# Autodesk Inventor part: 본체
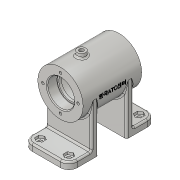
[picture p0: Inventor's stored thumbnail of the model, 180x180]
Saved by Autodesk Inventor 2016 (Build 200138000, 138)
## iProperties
Created: 2017-02
Part Number: 본체
Material: 알루미늄 6061
Document SubType Name: Modeling
Designer: H
Density: 2.7 g/cm^3
Appearance: 알루미늄 - 평지
Mass: 354.698 g
Surface Area: 422.999 cm^2
Volume: 131.37 cm^3
Author: H
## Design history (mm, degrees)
sketch "스케치2"
  geometry: C1 r 27 at (0, 0); 1 further point
  constraints: 1 centre point, 1 coincident
  dimensions: "d0" = 54 diameter of C1
extrude "돌출1" new body sketch "스케치2" stored distance "d1" = 70; taper "d2" = 0 deg
sketch "스케치4"
  geometry: L1 (-27, -35)-(27, -35) reference; L2 (27, 35)-(-27, 35) reference; L3 (0, 0)-(-60, 0); L4 (-60, 0)-(-60, 52); L5 (-60, 52)-(-52, 52); L6 (-52, 52)-(-52, 17); L7 (-52, 17)-(-60, 17) reference; L8 (-60, 17)-(-60, 52); L9 (27, -35)-(27, 35) reference; L10 (-60, -52)-(-52, -52); L11 (-52, -52)-(-52, -17); L12 (-52, -17)-(-60, -17); L13 (-60, -17)-(-60, -52)
  constraints: 20 end point, 4 symmetric about line, 3 horizontal, 2 vertical, 1 collinear, 1 perpendicular, 1 point on line
  dimensions: "d11" = 60 distance of L3.start L3.end; "d12" = 52 distance of L3.end L4.end; "d13" = 8 distance of L4.end L5.end
extrude "돌출2" join sketch "스케치4" stored distance "d17" = 54; taper "d18" = 0 deg
sketch "스케치7"
  geometry: L1 (20.591, 15)-(32, 15); L2 (32, 15)-(32, 10); L3 (32, 10)-(27, 10); L4 (-27, -35)-(27, -35) reference; L5 (27, 35)-(-27, 35) reference; L6 (27, -35)-(27, 35) reference; L7 (20.591, 15)-(20.591, 10); L8 (27, 10)-(20.591, 10); 2 further points
  constraints: 10 end point, 2 perpendicular, 1 horizontal, 1 vertical
  dimensions: "d27" = 25 vertical distance of L2.end point (27, 35); "d28" = 5 distance from line of L6 L2.end; "d108" = 25 vertical distance of point (27, 35) L7.end; "d109" = 20 vertical distance of point (27, 35) L1.end; "d110" = 11.40892 distance between parallel lines of L7 L2
revolve "회전1" sketch "스케치7" stored, may be unused: angle "d31" = 90 deg
sketch "스케치8"
  geometry: L1 (-52, -52)-(-52, -60) reference; L2 (-52, -60)-(-17, -60) reference; L3 (-17, -60)-(-17, -52) reference; L4 (-17, -52)-(-52, -52) reference; L5 (-17, -52)-(-25, -52); L6 (-17, -52)-(-17, 0); L7 (-17, 0)-(-25, 0); L8 (-25, 0)-(-25, -52); 1 further point
  constraints: 8 end point, 1 collinear, 1 horizontal, 1 perpendicular, 1 point on line, 1 vertical
  dimensions: "d33" = 8 distance of L6.end L7.end; "d36" = 52 distance of L3.end L6.end
extrude "돌출3" join sketch "스케치8" distance "d34" = 54; taper "d35" = 0 deg
sketch "스케치10"
  geometry: C1 r 16 at (0, 0); 1 further point
  constraints: 1 centre point, 1 coincident
  dimensions: "d37" = 32 diameter of C1
extrude "돌출4" cut sketch "스케치10" distance "d38" = 12; taper "d39" = 0 deg
sketch "스케치11"
  geometry: C1 r 14 at (0, 0); 1 further point
  constraints: 1 centre point, 1 coincident
  dimensions: "d40" = 28 diameter of C1
extrude "돌출5" cut sketch "스케치11" distance "d41" = 3; taper "d42" = 0 deg
sketch "스케치15" dims "d52" = 42
  geometry: 3 further points
  constraints: 1 coincident, 1 vertical alignment, 2 other
hole "구멍1" sketch "스케치15" at (0, 21) diameter "d53" = 3.242; stored, may be unused: countersink angle "d57" = 90 deg, drill point angle "d59" = 118 deg; dims "d54" = 8, "d55" = 4, "d56" = 2, "d58" = 10
sketch "스케치17"
  geometry: C1 r 5 at (0, 0) reference; 2 further points
  constraints: 1 coincident
hole "구멍2" sketch "스케치17" at (0, 0) diameter "d63" = 5.188; stored, may be unused: countersink angle "d67" = 90 deg, drill point angle "d69" = 118 deg; dims "d64" = 20, "d65" = 4, "d66" = 2, "d68" = 20
sketch "스케치18"
  geometry: L1 (0, 0)-(-18.991, -29.244); L2 (0, 0)-(0, -30.49); L3 (0, 0)-(-5.032, 3.268); L4 (-5.032, 3.268)-(-21.371, -21.892); L5 (-21.371, -21.892)-(-16.339, -25.16); C1 r 1.621 at (-21, 0) reference; C2 r 1.621 at (0, -21) reference; C3 r 1.621 at (21, 0) reference; C4 r 1.621 at (0, 21) reference; C5 r 16 at (0, 0) reference; C6 r 27 at (0, 0) reference; 1 further point
  constraints: 10 end point, 2 perpendicular, 1 point on line, 1 vertical
  dimensions: "d70" = 33 deg angle of L2 L1; "d71" = 30 distance of L3.end L4.end; "d72" = 12 diameter of L4.end L1; "d73" = 12 diameter of L3.end L1
revolve "회전2" sketch "스케치18" stored, may be unused: angle "d74" = 90 deg
sketch "스케치19"
  geometry: C1 r 22 at (0, 0); 1 further point
  constraints: 1 centre point, 1 coincident
  dimensions: "d75" = 44 diameter of C1
extrude "돌출9" cut sketch "스케치19" distance "d76" = 40; taper "d77" = 0 deg
sketch "스케치20"
  geometry: 2 further points
  constraints: 1 coincident
hole "구멍3" sketch "스케치20" at (0, 0) diameter "d78" = 5.188; stored, may be unused: countersink angle "d82" = 90 deg, drill point angle "d84" = 118 deg; dims "d79" = 20, "d80" = 4, "d81" = 2, "d83" = 20
fillet "모깎기1" dims "d85" = 10
sketch "스케치22" dims "d86" = 9
  geometry: L1 (44, 27)-(10, 27) reference; L2 (54, -8)-(54, 17) reference; L3 (0, -8)-(54, -8) reference; L4 (0, 17)-(0, -8) reference; L5 (0, -42)-(0, -67) reference; L6 (54, -42)-(0, -42) reference; L7 (54, -67)-(54, -42) reference; L8 (10, -77)-(44, -77) reference; L9 (5.5, 19.598)-(10, 22.196); L10 (10, 22.196)-(14.5, 19.598); L11 (14.5, 19.598)-(14.5, 14.402); L12 (14.5, 14.402)-(10, 11.804); L13 (10, 11.804)-(5.5, 14.402); L14 (5.5, 14.402)-(5.5, 19.598); A1 r 10 centre (10, 17) between (10, 27) and (0, 17) reference; A2 r 10 centre (44, 17) between (54, 17) and (44, 27) reference; A3 r 10 centre (10, -67) between (0, -67) and (10, -77) reference; A4 r 10 centre (44, -67) between (44, -77) and (54, -67) reference; 4 further points
  constraints: 12 end point, 2 coincident, 1 horizontal alignment, 1 midpoint, 1 vertical alignment, 15 other
extrude "돌출10" cut sketch "스케치22" distance "d87" = 3; taper "d88" = 0 deg
sketch "스케치23"
  geometry: L1 (44, 27)-(10, 27) reference; L2 (54, -8)-(54, 17) reference; L3 (0, -8)-(54, -8) reference; L4 (0, 17)-(0, -8) reference; C1 r 2.5 at (10, 17); A1 r 10 centre (10, 17) between (10, 27) and (0, 17) reference; A2 r 10 centre (44, 17) between (54, 17) and (44, 27) reference; 1 further point
  constraints: 1 centre point, 1 coincident
  dimensions: "d89" = 5 diameter of C1
extrude "돌출11" cut sketch "스케치23" stored distance "d90" = 3; taper "d91" = 0 deg
fillet "모깎기2" dims "d92" = 2
fillet "모깎기4" dims "d94" = 2
fillet "모깎기5" dims "d95" = 2
chamfer "모따기1" distance "d96" = 1; stored, may be unused: second distance "d97" = 2, angle "d98" = 45 deg
fillet "모깎기6" dims "d99" = 0.3
fillet "모깎기7" dims "d100" = 3
node "작업 평면1"
sketch "스케치24"
  geometry: L1 (27, -35)-(27, 35) reference; 2 further points
  constraints: 1 other
  dimensions: "d102" = 27 distance from line of L1 point (0, 0); "d103" = 0 distance of point (0, 0) point (0, 0)
feature "엠보싱1" sketch "스케치24" dims "d0" = 54, "d104" = 0.5, "d105" = 0
fillet "모깎기8" dims "d106" = 2
fillet "모깎기9" dims "d107" = 2
node "솔리드1"
mirror "대칭1"
pattern_circular "원형 패턴1" dims angle "d61" = 360 deg
mirror "대칭3"
mirror "대칭4"
mirror "대칭5"
mirror "대칭6"
node "투영된 루프2"
node "투영된 루프5"
node "투영된 루프6"
node "투영된 루프7"
node "투영된 루프8"
node "투영된 루프9"
node "투영된 루프10"
other parameters: "d101" = 50.75
